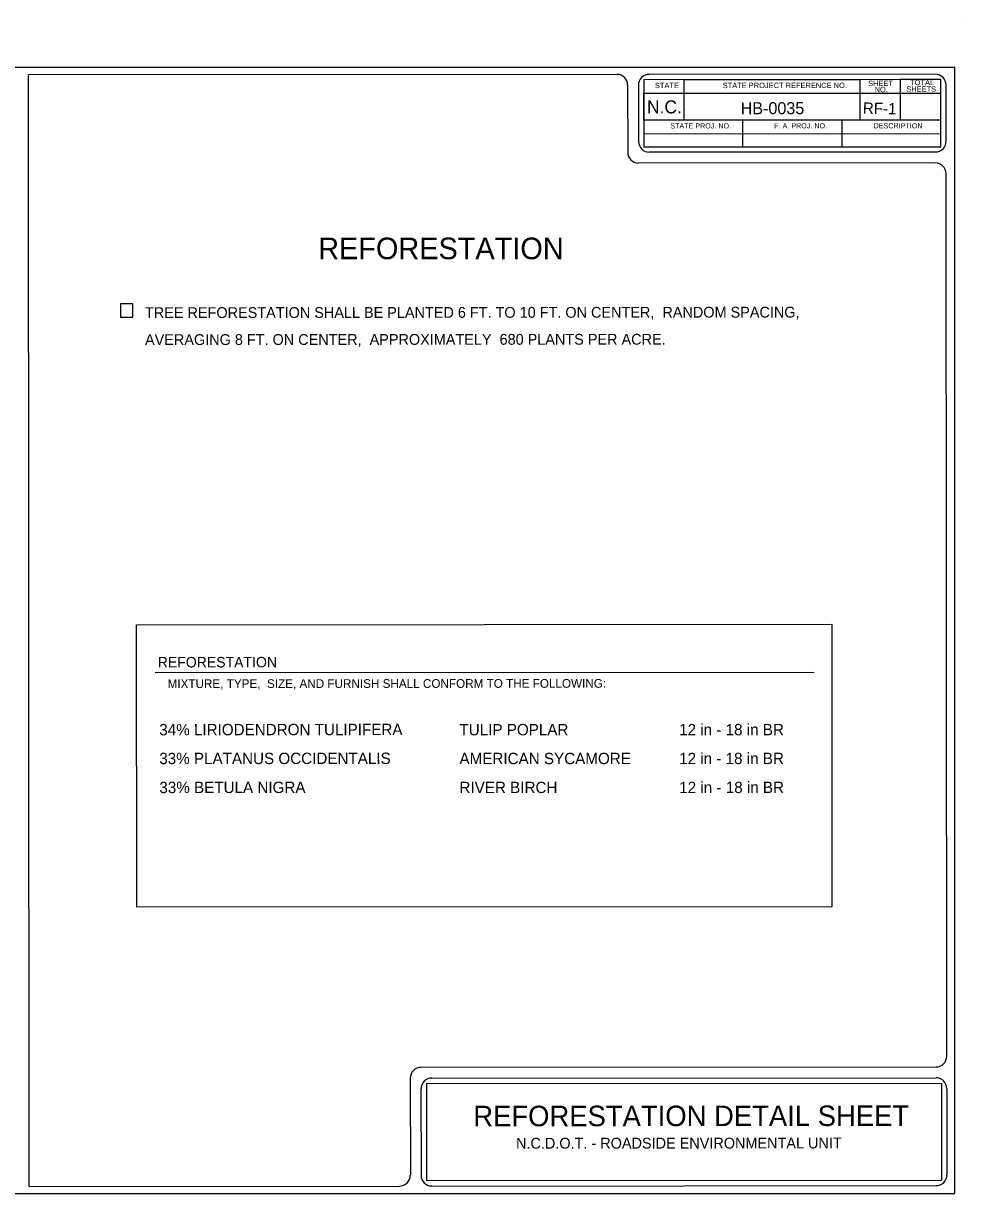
# Model space of a CAD drawing. Extents: x 1728110 to 1729925, y 1284214 to 1285339.
# Drawn here: x 1729070 to 1729925, y 1284272 to 1285339 of the extents above; entities that cross this region are included whole.
import ezdxf

# ---------------------------------------------------------------- set-up
doc = ezdxf.new("R2010")
doc.units = 0
doc.layers.add('Reforestation Detail CELL', color=7, linetype='Continuous')

msp = doc.modelspace()

# ---------------------------------------------------------------- linework, layer by layer
at = {"layer": 'Reforestation Detail CELL'}
for p, q in [((1729924.9, 1285339), (1729924.9, 1285339)), ((1729900.9, 1285292.7), (1729640.1, 1285292.5)), ((1729610.6, 1285292.5), (1729074.1, 1285292.1)), ((1729074.8, 1284278.3), (1729074.1, 1285292.1)), ((1729620.4, 1285282.7), (1729620.5, 1285221.5)), ((1729630.3, 1285282.7), (1729630.3, 1285231.4)), ((1729905.9, 1285287.8), (1729635.2, 1285287.6)), ((1729635.2, 1285287.6), (1729635.2, 1285226.1)), ((1729672.1, 1285287.6), (1729832, 1285287.8)), ((1729672.1, 1285250.7), (1729672.1, 1285287.6)), ((1729832, 1285287.8), (1729832.1, 1285250.9)), ((1729905.9, 1285275.5), (1729905.9, 1285287.8)), ((1729910.8, 1285231.6), (1729910.8, 1285282.9)), ((1729635.2, 1285275.3), (1729905.9, 1285275.5)), ((1729635.2, 1285250.7), (1729635.2, 1285275.3)), ((1729905.9, 1285250.9), (1729635.2, 1285250.7)), ((1729725.4, 1285250.8), (1729672.1, 1285250.7)), ((1729725.4, 1285226.2), (1729725.4, 1285250.8)), ((1729832.1, 1285250.9), (1729815.6, 1285250.8)), ((1729815.6, 1285250.8), (1729815.7, 1285226.2)), ((1729905.9, 1285238.6), (1729905.9, 1285250.9)), ((1729635.2, 1285238.4), (1729905.9, 1285238.6)), ((1729905.9, 1285226.3), (1729635.2, 1285226.1)), ((1729901, 1285221.7), (1729640.2, 1285221.5)), ((1729901, 1285211.9), (1729630.3, 1285211.7)), ((1729911.4, 1284397.1), (1729910.8, 1285202)), ((1729189.7, 1284746.9), (1729790.4, 1284747.3)), ((1729432, 1284386.9), (1729901.6, 1284387.2)), ((1729422.2, 1284377), (1729422.3, 1284288.4)), ((1729441.9, 1284377), (1729901.6, 1284377.4)), ((1729432, 1284367.2), (1729432.1, 1284288.5)), ((1729437, 1284372.1), (1729906.5, 1284372.5)), ((1729437, 1284372.1), (1729437, 1284283.5)), ((1729906.5, 1284372.5), (1729906.6, 1284283.9)), ((1729911.5, 1284367.6), (1729911.5, 1284288.8)), ((1729437, 1284283.5), (1729906.6, 1284283.9)), ((1729442, 1284278.6), (1729901.7, 1284279)), ((1729074.8, 1284278.3), (1729412.4, 1284278.6))]:
    msp.add_line(p, q, dxfattribs=at)
for points in [[(1729918.8, 1285298.9), (1728252.2, 1285298.9), (1728252.2, 1284271.7), (1729918.8, 1284271.7)], [(1729169.3, 1285083.3), (1729157.9, 1285083.3), (1729158, 1285071.1), (1729169.3, 1285071.1)], [(1729172.6, 1284790.6), (1729806.5, 1284791.1), (1729806.7, 1284533.3), (1729172.8, 1284532.9)]]:
    msp.add_lwpolyline(points, close=True, dxfattribs=at)
msp.add_lwpolyline([(1729905.9, 1285226.3), (1729905.9, 1285287.8), (1729868.9, 1285287.8), (1729869, 1285250.9)], dxfattribs=at)
for centre, start, end in [((1729900.9, 1285282.9), 0.0429, 90.0429), ((1729610.6, 1285282.7), 0.0429, 90.0429), ((1729640.1, 1285282.7), 90.0429, 180.0429), ((1729640.2, 1285231.4), 180.0429, 270.0429), ((1729901, 1285231.6), 270.0429, 0.0429), ((1729630.3, 1285221.5), 180.0429, 270.0429), ((1729901, 1285202), 0.0429, 90.0429), ((1729901.6, 1284397.1), 270.0429, 0.0429), ((1729432, 1284377), 90.0429, 180.0429), ((1729441.9, 1284367.2), 90.0429, 180.0429), ((1729901.6, 1284367.5), 0.0429, 90.0429), ((1729412.4, 1284288.4), 270.0429, 0.0429), ((1729441.9, 1284288.5), 180.0429, 270.0429), ((1729901.7, 1284288.8), 270.0429, 0.0429)]:
    msp.add_arc(centre, 9.84, start, end, dxfattribs=at)

# ---------------------------------------------------------------- texts
for s, height, rotation, p in [('STATE', 4.92, 0.0429, (1729645.3, 1285280)), ('STATE PROJECT REFERENCE NO.', 4.921, 0.0429, (1729707.1, 1285280)), ('SHEET', 4.92, 0.0429, (1729839.7, 1285281.9)), ('TOTAL', 4.92, 0.0429, (1729878, 1285282.7)), ('NO.', 4.92, 0.0429, (1729845.6, 1285276.3)), ('SHEETS', 4.92, 0.0429, (1729874.5, 1285276.7)), ('N.C.', 11.86, 0.0429, (1729638.1, 1285256.9)), ('HB-0035', 10.98, 0.0429, (1729723.5, 1285256.2)), ('RF-1', 10.32, 358.6769, (1729834.8, 1285256.7)), ('STATE PROJ. NO.', 4.724, 0.0429, (1729659.3, 1285243.2)), ('F. A. PROJ. NO.', 4.724, 0.0429, (1729754.1, 1285243.3)), ('DESCRIPTION', 4.724, 0.0429, (1729844.7, 1285243.3)), ('REFORESTATION', 19.685, 360, (1729338.3, 1285124)), ('TREE REFORESTATION SHALL BE PLANTED 6 FT. TO 10 FT. ON CENTER,  RANDOM SPACING,', 9.843, 0.0429, (1729180.4, 1285070.3)), ('AVERAGING 8 FT. ON CENTER,  APPROXIMATELY  680 PLANTS PER ACRE. ', 9.843, 0.0429, (1729180.4, 1285045.7)), ('REFORESTATION ', 9.567, 0.0429, (1729192, 1284751.6)), ('MIXTURE, TYPE,  SIZE, AND FURNISH SHALL CONFORM TO THE FOLLOWING:', 7.972, 0.0429, (1729201, 1284732.8)), ('34% LIRIODENDRON TULIPIFERA', 10.363, 0.0429, (1729193.4, 1284689.7)), ('TULIP POPLAR', 10.363, 360, (1729467.1, 1284689.7)), ('12 in - 18 in BR', 10.363, 0.0429, (1729667.4, 1284689.7)), ('33% PLATANUS OCCIDENTALIS', 10.363, 0.0429, (1729193.4, 1284663.4)), ('AMERICAN SYCAMORE', 10.363, 360, (1729467.1, 1284663.4)), ('12 in - 18 in BR', 10.363, 0.0429, (1729667.4, 1284663.4)), ('33% BETULA NIGRA', 10.363, 0.0429, (1729193.5, 1284637)), ('RIVER BIRCH', 10.363, 360, (1729467.1, 1284637)), ('12 in - 18 in BR', 10.363, 0.0429, (1729667.5, 1284637)), ('REFORESTATION DETAIL SHEET', 18.7, 0.0429, (1729479.7, 1284333.1)), ('N.C.D.O.T. - ROADSIDE ENVIRONMENTAL UNIT', 9.843, 0.0429, (1729518.7, 1284312.7))]:
    msp.add_text(s, height=height, rotation=rotation, dxfattribs=at).set_placement(p)

doc.saveas('drawing.dxf')
